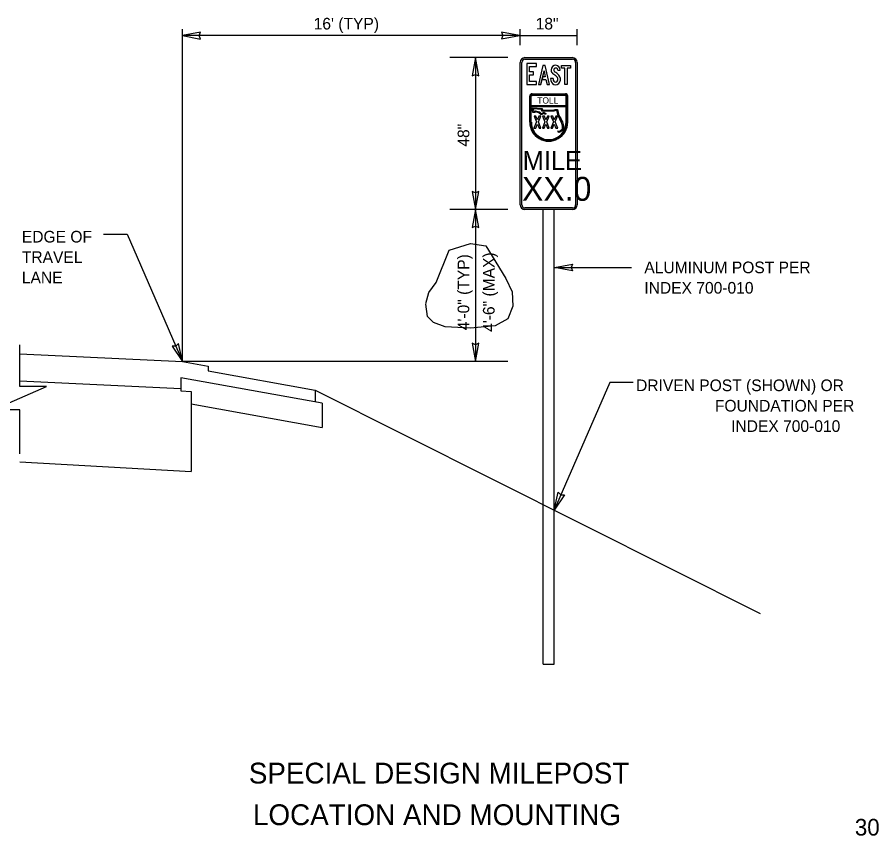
# Model space of a CAD drawing. Extents: x 56768 to 57406, y 11696 to 12105.
# Drawn here: x 57187.3 to 57394.2, y 11706.5 to 11903.1 of the extents above; entities that cross this region are included whole.
import ezdxf

# ---------------------------------------------------------------- set-up
doc = ezdxf.new("R2010")
doc.units = 0
for name, color, linetype in [('1', 7, 'Continuous'), ('52', 7, 'Continuous'), ('62', 7, 'Continuous'), ('Default', 7, 'Continuous'), ('DimLines_dp', 7, 'Continuous'), ('SignPanel', 7, 'Continuous'), ('TextMisc', 7, 'Continuous'), ('TextShtNo', 7, 'Continuous'), ('XSGrdLine_ex', 7, 'Continuous')]:
    doc.layers.add(name, color=color, linetype=linetype)

msp = doc.modelspace()

# ---------------------------------------------------------------- linework, layer by layer
at = {"layer": '1'}
for p, q in [((57313.6, 11786.05), (57313.6, 11856.93)), ((57316.26, 11784.71), (57316.26, 11856.93)), ((57313.6, 11747.72), (57313.6, 11786.05)), ((57316.26, 11747.72), (57316.26, 11784.71)), ((57313.6, 11747.72), (57316.26, 11747.72))]:
    msp.add_line(p, q, dxfattribs=at)
at = {"layer": '52'}
msp.add_line((57305.09, 11820.43), (57226.97, 11820.43), dxfattribs=at)
at = {"layer": '62'}
msp.add_lwpolyline([(57285.44, 11834.37), (57286.14, 11836.97), (57287.94, 11839.37), (57291.04, 11847.13), (57296.14, 11848.73), (57299.84, 11848.23), (57304.65, 11840.37), (57306.15, 11837.17), (57306.35, 11833.67), (57305.15, 11830.66), (57302.05, 11828.96), (57296.14, 11828.46), (57290.04, 11828.76), (57287.24, 11829.76), (57285.84, 11831.26), (57285.44, 11834.17)], dxfattribs=at)
at = {"layer": 'Default'}
msp.add_lwpolyline([(57187.88, 11798.24), (57187.88, 11808.8), (57181.42, 11808.8), (57187.88, 11811.61), (57194.34, 11814.43), (57187.88, 11814.43), (57187.88, 11824.43)], dxfattribs=at)
at = {"layer": 'DimLines_dp'}
for p, q in [((57226.97, 11820.43), (57226.97, 11900.25)), ((57308.09, 11896.42), (57308.09, 11900.25)), ((57321.78, 11896.42), (57321.78, 11900.25)), ((57231.32, 11899.52), (57226.97, 11898.71)), ((57308.09, 11898.71), (57226.97, 11898.71)), ((57226.97, 11898.71), (57231.32, 11897.87)), ((57230.99, 11898.71), (57231.32, 11899.52)), ((57231.32, 11897.87), (57230.99, 11898.71)), ((57307.91, 11898.71), (57303.56, 11899.55)), ((57303.56, 11899.55), (57303.89, 11898.71)), ((57303.89, 11898.71), (57303.56, 11897.9)), ((57303.56, 11897.9), (57307.91, 11898.71)), ((57308.09, 11898.71), (57321.78, 11898.71)), ((57305.09, 11893.42), (57291.17, 11893.42)), ((57297.35, 11893.42), (57296.51, 11889.07)), ((57297.35, 11893.42), (57297.35, 11856.93)), ((57298.16, 11889.07), (57297.35, 11893.42)), ((57296.51, 11889.07), (57297.35, 11889.4)), ((57297.35, 11889.4), (57298.16, 11889.07)), ((57297.35, 11860.95), (57296.54, 11861.28)), ((57296.54, 11861.28), (57297.35, 11856.93)), ((57297.35, 11860.95), (57296.54, 11861.28)), ((57296.54, 11861.28), (57297.35, 11856.93)), ((57297.35, 11856.93), (57298.19, 11861.28)), ((57298.19, 11861.28), (57297.35, 11860.95)), ((57297.35, 11856.93), (57298.19, 11861.28)), ((57298.19, 11861.28), (57297.35, 11860.95)), ((57305.09, 11856.93), (57291.17, 11856.93)), ((57297.35, 11856.93), (57296.51, 11852.58)), ((57297.35, 11856.93), (57297.35, 11820.43)), ((57298.16, 11852.58), (57297.35, 11856.93)), ((57296.51, 11852.58), (57297.35, 11852.91)), ((57297.35, 11852.91), (57298.16, 11852.58)), ((57208.01, 11851.04), (57213.65, 11851.04)), ((57213.65, 11851.04), (57226.97, 11820.42)), ((57316.32, 11842.98), (57320.67, 11843.82)), ((57316.32, 11842.98), (57334.84, 11842.98)), ((57320.67, 11842.17), (57316.32, 11842.98)), ((57320.67, 11843.82), (57320.34, 11842.98)), ((57320.34, 11842.98), (57320.67, 11842.17)), ((57225.37, 11824.11), (57224.49, 11824.09)), ((57224.49, 11824.09), (57226.97, 11820.42)), ((57226.01, 11824.75), (57225.37, 11824.11)), ((57226.97, 11820.42), (57226.01, 11824.75)), ((57297.35, 11824.45), (57296.54, 11824.78)), ((57296.54, 11824.78), (57297.35, 11820.43)), ((57297.35, 11820.43), (57298.19, 11824.78)), ((57298.19, 11824.78), (57297.35, 11824.45)), ((57329.59, 11815.33), (57316.26, 11784.71)), ((57335.23, 11815.33), (57329.59, 11815.33)), ((57316.26, 11784.71), (57317.23, 11789.03)), ((57317.23, 11789.03), (57317.87, 11788.4)), ((57318.74, 11788.38), (57316.26, 11784.71)), ((57317.87, 11788.4), (57318.74, 11788.38))]:
    msp.add_line(p, q, dxfattribs=at)
at = {"layer": 'SignPanel'}
for p, q in [((57317.13, 11890.42), (57317.71, 11890.42)), ((57317.13, 11890.42), (57317.71, 11890.42)), ((57317.13, 11890.42), (57317.71, 11890.42)), ((57315.99, 11888.38), (57315.4, 11888.38)), ((57315.99, 11888.38), (57315.4, 11888.38)), ((57315.99, 11888.38), (57315.4, 11888.38)), ((57310.37, 11877.91), (57310.37, 11884.19)), ((57310.57, 11877.91), (57310.57, 11884.19)), ((57310.75, 11881.91), (57310.75, 11884.19)), ((57310.94, 11884.76), (57318.93, 11884.76)), ((57310.94, 11884.56), (57318.93, 11884.56)), ((57310.94, 11884.37), (57318.93, 11884.37)), ((57319.12, 11881.91), (57319.12, 11884.19)), ((57319.31, 11877.91), (57319.31, 11884.19)), ((57319.5, 11877.91), (57319.5, 11884.19)), ((57310.75, 11881.91), (57319.12, 11881.91)), ((57310.75, 11877.91), (57310.75, 11881.71)), ((57310.75, 11881.71), (57319.12, 11881.71)), ((57319.12, 11877.91), (57319.12, 11881.71)), ((57311.14, 11880.26), (57310.97, 11881.35)), ((57310.97, 11881.35), (57313.35, 11881.16)), ((57311.59, 11880.2), (57311.14, 11880.26)), ((57313.19, 11880.95), (57311.24, 11881.1)), ((57311.24, 11881.1), (57311.34, 11880.46)), ((57311.34, 11880.46), (57311.53, 11880.44)), ((57311.53, 11880.44), (57311.8, 11880.65)), ((57311.84, 11880.4), (57311.59, 11880.2)), ((57311.8, 11880.65), (57312.71, 11880.36)), ((57312.6, 11880.15), (57311.84, 11880.4)), ((57312.23, 11881.01), (57312.23, 11881.01)), ((57313.13, 11879.65), (57312.6, 11880.15)), ((57312.71, 11880.36), (57313.17, 11879.94)), ((57313.77, 11880.03), (57313.13, 11879.65)), ((57313.17, 11879.94), (57313.78, 11880.3)), ((57313.32, 11880.59), (57313.19, 11880.95)), ((57316.33, 11880.59), (57313.32, 11880.59)), ((57313.35, 11881.16), (57313.48, 11880.82)), ((57313.48, 11880.82), (57316.21, 11880.82)), ((57314.15, 11879.77), (57313.77, 11880.03)), ((57313.78, 11880.3), (57314.27, 11879.96)), ((57314.27, 11879.96), (57314.15, 11879.77)), ((57316.21, 11880.82), (57316.31, 11880.97)), ((57316.31, 11880.97), (57317.05, 11880.97)), ((57316.44, 11880.74), (57316.33, 11880.59)), ((57316.87, 11880.74), (57316.44, 11880.74)), ((57317.17, 11879.45), (57316.87, 11880.74)), ((57317.05, 11880.97), (57317.38, 11879.54)), ((57317.38, 11879.54), (57317.83, 11878.81)), ((57317.6, 11878.75), (57317.17, 11879.45)), ((57317.6, 11878.57), (57317.6, 11878.75)), ((57318.03, 11877.86), (57317.6, 11878.57)), ((57317.83, 11878.81), (57317.83, 11878.63)), ((57317.83, 11878.63), (57318.24, 11877.96)), ((57318.27, 11877), (57318.03, 11877.86)), ((57318.24, 11877.96), (57318.5, 11877.03)), ((57317.16, 11875.63), (57317.29, 11875.82)), ((57317.39, 11875.47), (57317.16, 11875.63)), ((57317.29, 11875.82), (57317.43, 11875.72)), ((57317.74, 11875.56), (57317.39, 11875.47)), ((57317.43, 11875.72), (57317.64, 11875.77)), ((57317.64, 11875.77), (57318.27, 11876.28)), ((57318.5, 11876.17), (57317.74, 11875.56)), ((57318.27, 11876.28), (57318.27, 11877)), ((57318.5, 11877.03), (57318.5, 11876.17))]:
    msp.add_line(p, q, dxfattribs=at)
for points in [[(57308.09, 11858.07), (57308.09, 11892.28)], [(57308.47, 11858.07), (57308.47, 11892.28)], [(57309.23, 11893.42), (57320.64, 11893.42)], [(57309.23, 11893.04), (57320.64, 11893.04)], [(57321.4, 11892.28), (57321.4, 11858.07)], [(57321.78, 11892.28), (57321.78, 11858.07)], [(57320.64, 11857.31), (57309.23, 11857.31)], [(57320.64, 11856.93), (57309.23, 11856.93)]]:
    msp.add_lwpolyline(points, dxfattribs=at)
for points in [[(57310.29, 11887.65), (57310.29, 11889.27), (57311.31, 11889.27), (57311.31, 11889.98), (57310.29, 11889.98), (57310.29, 11891.3), (57312.02, 11891.3), (57312.02, 11892), (57309.64, 11892), (57309.64, 11886.94), (57312.02, 11886.94), (57312.02, 11887.65)], [(57310.29, 11887.65), (57310.29, 11889.27), (57311.31, 11889.27), (57311.31, 11889.98), (57310.29, 11889.98), (57310.29, 11891.3), (57312.02, 11891.3), (57312.02, 11892), (57309.64, 11892), (57309.64, 11886.94), (57312.02, 11886.94), (57312.02, 11887.65)], [(57310.29, 11887.65), (57310.29, 11889.27), (57311.31, 11889.27), (57311.31, 11889.98), (57310.29, 11889.98), (57310.29, 11891.3), (57312.02, 11891.3), (57312.02, 11892), (57309.64, 11892), (57309.64, 11886.94), (57312.02, 11886.94), (57312.02, 11887.65)], [(57314.26, 11888.17), (57314.54, 11886.94), (57315.14, 11886.94), (57314.12, 11891.52), (57313.49, 11891.52), (57312.47, 11886.94), (57313.08, 11886.94), (57313.35, 11888.17)], [(57313.49, 11888.81), (57313.35, 11888.17), (57314.26, 11888.17), (57314.54, 11886.94), (57315.14, 11886.94), (57314.12, 11891.52), (57313.49, 11891.52), (57312.47, 11886.94), (57313.08, 11886.94), (57313.81, 11890.21), (57314.12, 11888.81)], [(57313.49, 11888.81), (57313.35, 11888.17), (57314.26, 11888.17), (57314.54, 11886.94), (57315.14, 11886.94), (57314.12, 11891.52), (57313.49, 11891.52), (57312.47, 11886.94), (57313.08, 11886.94), (57313.81, 11890.21), (57314.12, 11888.81)], [(57313.81, 11890.21), (57314.12, 11888.81), (57313.49, 11888.81)], [(57318.77, 11890.88), (57318, 11890.88), (57318, 11891.52), (57320.14, 11891.52), (57320.14, 11890.88), (57319.36, 11890.88), (57319.36, 11886.94), (57318.77, 11886.94)], [(57318.77, 11890.88), (57318, 11890.88), (57318, 11891.52), (57320.14, 11891.52), (57320.14, 11890.88), (57319.36, 11890.88), (57319.36, 11886.94), (57318.77, 11886.94)], [(57318.77, 11890.88), (57318, 11890.88), (57318, 11891.52), (57320.14, 11891.52), (57320.14, 11890.88), (57319.36, 11890.88), (57319.36, 11886.94), (57318.77, 11886.94)], [(57311.83, 11876.49), (57312.23, 11877.47), (57312.64, 11876.49), (57313.07, 11876.49), (57312.45, 11877.98), (57313.02, 11879.34), (57312.59, 11879.34), (57312.23, 11878.49), (57311.88, 11879.34), (57311.45, 11879.34), (57312.02, 11877.98), (57311.4, 11876.49)], [(57313.84, 11876.49), (57314.25, 11877.47), (57314.66, 11876.49), (57315.08, 11876.49), (57314.46, 11877.98), (57315.03, 11879.34), (57314.61, 11879.34), (57314.25, 11878.49), (57313.89, 11879.34), (57313.46, 11879.34), (57314.04, 11877.98), (57313.41, 11876.49)], [(57315.86, 11876.49), (57316.27, 11877.47), (57316.67, 11876.49), (57317.1, 11876.49), (57316.48, 11877.98), (57317.05, 11879.34), (57316.62, 11879.34), (57316.27, 11878.49), (57315.91, 11879.34), (57315.48, 11879.34), (57316.05, 11877.98), (57315.43, 11876.49)]]:
    msp.add_lwpolyline(points, close=True, dxfattribs=at)
for centre, radius, start, end in [((57309.23, 11892.28), 1.14, 90, 180), ((57309.23, 11892.28), 0.76, 90, 180), ((57320.64, 11892.28), 1.14, 0, 90), ((57320.64, 11892.28), 0.76, 0, 90), ((57309.23, 11858.07), 1.14, 180, 270), ((57309.23, 11858.07), 0.76, 180, 270), ((57320.64, 11858.07), 1.14, 270, 360), ((57320.64, 11858.07), 0.76, 270, 360)]:
    msp.add_arc(centre, radius, start, end, dxfattribs=at)
for centre, major_axis, ratio, start_param, end_param in [((57316.51, 11890.42), (0, 1.07), 0.91923, 1.534831, 2.511766), ((57316.51, 11890.42), (0, 1.07), 0.91923, 1.534831, 2.511766), ((57316.51, 11890.42), (0, 1.07), 0.91923, 1.534831, 2.511766), ((57316.62, 11890.39), (0, 1.19), 0.91923, 4.736267, 7.790596), ((57316.62, 11890.39), (0, 1.19), 0.91923, 4.736267, 7.790596), ((57316.62, 11890.39), (0, 1.19), 0.91923, 4.736267, 7.790596), ((57316.55, 11890.44), (0, 0.46), 0.91923, 0.87378, 2.656959), ((57316.55, 11890.44), (0, 0.46), 0.91923, 0.87378, 2.656959), ((57316.55, 11890.44), (0, 0.46), 0.91923, 0.87378, 2.656959), ((57316.62, 11890.37), (0, 0.558), 0.91923, 4.786904, 7.140738), ((57316.62, 11890.37), (0, 0.558), 0.91923, 4.786904, 7.140738), ((57316.62, 11890.37), (0, 0.558), 0.91923, 4.786904, 7.140738), ((57314.42, 11886.19), (0, 4.39), 0.91923, 5.462886, 5.782242), ((57314.42, 11886.19), (0, 4.39), 0.91923, 5.462886, 5.782242), ((57314.42, 11886.19), (0, 4.39), 0.91923, 5.462886, 5.782242), ((57316.77, 11888.31), (0, 1.5), 0.91923, 1.526364, 2.701682), ((57316.77, 11888.31), (0, 1.5), 0.91923, 1.526364, 2.701682), ((57316.77, 11888.31), (0, 1.5), 0.91923, 1.526364, 2.701682), ((57313.91, 11885.49), (0, 4.63), 0.91923, 5.515137, 5.786988), ((57313.91, 11885.49), (0, 4.63), 0.91923, 5.515137, 5.786988), ((57313.91, 11885.49), (0, 4.63), 0.91923, 5.515137, 5.786988), ((57316.83, 11888.33), (0, 0.911), 0.91923, 1.524757, 2.28214), ((57316.83, 11888.33), (0, 0.911), 0.91923, 1.524757, 2.28214), ((57316.83, 11888.33), (0, 0.911), 0.91923, 1.524757, 2.28214), ((57316.61, 11888.11), (0, 0.581), 0.91923, 2.261787, 4.23006), ((57316.61, 11888.11), (0, 0.581), 0.91923, 2.261787, 4.23006), ((57316.61, 11888.11), (0, 0.581), 0.91923, 2.261787, 4.23006), ((57316.43, 11888.19), (0, 0.792), 0.91923, 4.254409, 5.632398), ((57316.43, 11888.19), (0, 0.792), 0.91923, 4.254409, 5.632398), ((57316.43, 11888.19), (0, 0.792), 0.91923, 4.254409, 5.632398), ((57316.44, 11888.19), (0, 1.42), 0.91923, 4.260987, 5.485755), ((57316.44, 11888.19), (0, 1.42), 0.91923, 4.260987, 5.485755), ((57316.44, 11888.19), (0, 1.42), 0.91923, 4.260987, 5.485755), ((57316.58, 11888.12), (0, 1.24), 0.91923, 2.786047, 4.251692), ((57316.58, 11888.12), (0, 1.24), 0.91923, 2.786047, 4.251692), ((57316.58, 11888.12), (0, 1.24), 0.91923, 2.786047, 4.251692), ((57310.95, 11884.18), (0, 0.57), 0.9997, 0, 1.570796), ((57310.95, 11884.18), (0, 0.38), 0.9997, 0, 1.570796), ((57310.95, 11884.18), (0, 0.19), 0.9997, 0, 1.570796), ((57318.93, 11884.18), (0, 0.57), 0.9997, 4.712389, 6.283185), ((57318.93, 11884.18), (0, 0.38), 0.9997, 4.712389, 6.283185), ((57318.93, 11884.18), (0, 0.19), 0.9997, 4.712389, 6.283185), ((57314.94, 11877.91), (0, -4.56), 0.9997, 4.712389, 7.853982), ((57314.94, 11877.91), (0, -4.37), 0.9997, 4.712389, 7.853982), ((57314.94, 11877.91), (0, -4.18), 0.9997, 4.712389, 7.853982)]:
    msp.add_ellipse(centre, major_axis=major_axis, ratio=ratio, start_param=start_param, end_param=end_param, dxfattribs=at)
at = {"layer": 'XSGrdLine_ex'}
for p, q in [((57226.97, 11820.42), (57233.13, 11819.31)), ((57233.13, 11819.31), (57233.13, 11818.14)), ((57233.13, 11818.14), (57258.85, 11813.51)), ((57226.56, 11816.48), (57226.56, 11813.33)), ((57260.55, 11810.37), (57226.56, 11816.48)), ((57226.56, 11813.33), (57229.03, 11813.18)), ((57258.85, 11813.51), (57258.85, 11810.67)), ((57229.03, 11813.18), (57229.03, 11794)), ((57229.03, 11810.22), (57260.55, 11804.55)), ((57260.55, 11810.37), (57260.55, 11804.55)), ((57187.88, 11796.28), (57229.03, 11794))]:
    msp.add_line(p, q, dxfattribs=at)
for points in [[(57187.88, 11822.28), (57226.97, 11820.42)], [(57187.88, 11815.78), (57226.56, 11813.95)], [(57258.85, 11813.51), (57365.73, 11759.9)]]:
    msp.add_lwpolyline(points, dxfattribs=at)

# ---------------------------------------------------------------- texts
at = {"layer": 'DimLines_dp'}
for s, p in [("16' (TYP)", (57258.48, 11900.18)), ('18"', (57311.8, 11900.18)), ('EDGE OF ', (57188.39, 11849)), ('TRAVEL ', (57188.39, 11844.1)), ('ALUMINUM POST PER', (57337.9, 11841.62)), ('LANE', (57188.39, 11839.2)), ('INDEX 700-010', (57337.9, 11836.72)), ('DRIVEN POST (SHOWN) OR', (57335.91, 11813.29)), ('FOUNDATION PER', (57354.85, 11808.39)), ('INDEX 700-010', (57358.74, 11803.49))]:
    msp.add_text(s, height=2.8, dxfattribs=at).set_placement(p)
for s, p in [('48"', (57295.86, 11872.03)), ('4\'-6" (MAX)', (57301.94, 11827.53)), ('4\'-0" (TYP)', (57295.86, 11827.92))]:
    msp.add_text(s, height=2.8, rotation=90, dxfattribs=at).set_placement(p)
at = {"layer": 'SignPanel'}
for s, height, p in [('TOLL', 1.519, (57312.18, 11882.38)), ('MILE', 4.562, (57308.68, 11866.42))]:
    msp.add_text(s, height=height, dxfattribs=at).set_placement(p)
msp.add_text('XX.0', height=5.75, rotation=360, dxfattribs=at).set_placement((57308.52, 11859.02))
at = {"layer": 'TextMisc'}
for s, p in [('SPECIAL DESIGN MILEPOST ', (57242.9, 11719.02)), (' LOCATION AND MOUNTING  ', (57242.04, 11709.02))]:
    msp.add_text(s, height=5, rotation=360, dxfattribs=at).set_placement(p)
at = {"layer": 'TextShtNo'}
msp.add_text('30', height=4, rotation=360, dxfattribs=at).set_placement((57388.47, 11706.52))

doc.saveas('drawing.dxf')
